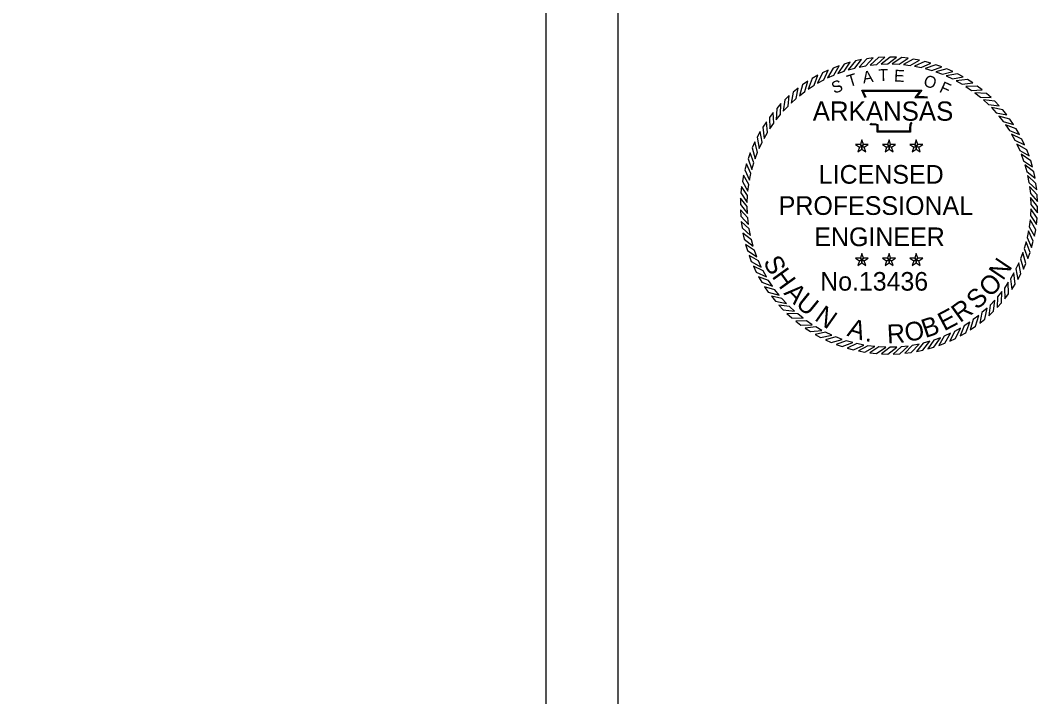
# Model space of a CAD drawing. Extents: x 759422 to 1402140, y 1662254 to 1956530.
# Drawn here: x 1401731.3 to 1402139.7, y 1955985.4 to 1956257.2 of the extents above; entities that cross this region are included whole.
import ezdxf

# ---------------------------------------------------------------- set-up
doc = ezdxf.new("R2010")
doc.units = 0
doc.layers.add('1', color=7, linetype='Continuous')
doc.layers.add('G-ANNO-SYMB', color=7, linetype='Continuous')

msp = doc.modelspace()

# ---------------------------------------------------------------- linework, layer by layer
at = {"layer": '1'}
msp.add_line((1401942.43, 1955459.2), (1401942.43, 1956501.52), dxfattribs=at)
msp.add_lwpolyline([(1401971.27, 1956530.36), (1400271.27, 1956530.36), (1400271.27, 1955430.36), (1401971.27, 1955430.36)], close=True, dxfattribs=at)
at = {"layer": 'G-ANNO-SYMB'}
for points in [[(1402073.67, 1956242.04), (1402071.13, 1956241.72), (1402068.01, 1956238.37), (1402070.73, 1956238.89)], [(1402078.34, 1956242.36), (1402075.78, 1956242.23), (1402072.41, 1956239.14), (1402075.17, 1956239.45)], [(1402083.03, 1956242.31), (1402080.46, 1956242.39), (1402076.86, 1956239.57), (1402079.63, 1956239.66)], [(1402087.69, 1956241.89), (1402085.14, 1956242.17), (1402081.33, 1956239.64), (1402084.1, 1956239.52)], [(1402060, 1956238.92), (1402057.6, 1956238), (1402055.35, 1956234.02), (1402057.88, 1956235.16)], [(1402064.47, 1956240.32), (1402062.01, 1956239.59), (1402059.45, 1956235.8), (1402062.06, 1956236.74)], [(1402069.04, 1956241.36), (1402066.53, 1956240.83), (1402063.68, 1956237.25), (1402066.35, 1956237.99)], [(1402092.31, 1956241.11), (1402089.79, 1956241.59), (1402085.79, 1956239.37), (1402088.54, 1956239.02)], [(1402096.86, 1956239.97), (1402094.38, 1956240.64), (1402090.22, 1956238.74), (1402092.93, 1956238.18)], [(1402101.3, 1956238.48), (1402098.88, 1956239.34), (1402094.58, 1956237.77), (1402097.24, 1956237)], [(1402105.6, 1956236.64), (1402103.26, 1956237.69), (1402098.86, 1956236.46), (1402101.45, 1956235.48)], [(1402051.46, 1956235.09), (1402049.23, 1956233.81), (1402047.63, 1956229.53), (1402049.95, 1956231.05)], [(1402055.65, 1956237.17), (1402053.33, 1956236.07), (1402051.4, 1956231.93), (1402053.83, 1956233.26)], [(1402109.75, 1956234.47), (1402107.5, 1956235.69), (1402103.01, 1956234.82), (1402105.52, 1956233.64)], [(1402043.62, 1956229.97), (1402041.62, 1956228.36), (1402040.71, 1956223.88), (1402042.76, 1956225.75)], [(1402047.44, 1956232.68), (1402045.32, 1956231.24), (1402044.06, 1956226.84), (1402046.25, 1956228.54)], [(1402113.72, 1956231.98), (1402111.57, 1956233.38), (1402107.03, 1956232.86), (1402109.44, 1956231.49)], [(1402117.48, 1956229.18), (1402115.45, 1956230.75), (1402110.88, 1956230.59), (1402113.17, 1956229.03)], [(1402040.02, 1956226.97), (1402038.16, 1956225.2), (1402037.6, 1956220.67), (1402039.5, 1956222.69)], [(1402121.01, 1956226.1), (1402119.11, 1956227.82), (1402114.54, 1956228.02), (1402116.7, 1956226.29)], [(1402036.68, 1956223.69), (1402034.95, 1956221.79), (1402034.75, 1956217.22), (1402036.49, 1956219.38)], [(1402124.29, 1956222.75), (1402122.53, 1956224.62), (1402117.99, 1956225.18), (1402120.01, 1956223.28)], [(1402127.29, 1956219.16), (1402125.68, 1956221.16), (1402121.2, 1956222.07), (1402123.07, 1956220.02)], [(1402033.6, 1956220.16), (1402032.03, 1956218.13), (1402032.19, 1956213.56), (1402033.75, 1956215.85)], [(1402130.01, 1956215.34), (1402128.56, 1956217.46), (1402124.16, 1956218.72), (1402125.86, 1956216.53)], [(1402030.8, 1956216.4), (1402029.4, 1956214.25), (1402029.92, 1956209.71), (1402031.29, 1956212.12)], [(1402132.41, 1956211.32), (1402131.13, 1956213.54), (1402126.85, 1956215.15), (1402128.37, 1956212.83)], [(1402028.31, 1956212.43), (1402027.08, 1956210.18), (1402027.95, 1956205.69), (1402029.13, 1956208.2)], [(1402069.14, 1956206.48), (1402069.75, 1956207.33), (1402069.14, 1956209.21), (1402068.53, 1956207.33)], [(1402080.05, 1956206.48), (1402080.66, 1956207.33), (1402080.05, 1956209.21), (1402079.44, 1956207.33)], [(1402090.96, 1956206.48), (1402091.57, 1956207.33), (1402090.96, 1956209.21), (1402090.35, 1956207.33)], [(1402134.49, 1956207.12), (1402133.39, 1956209.44), (1402129.25, 1956211.37), (1402130.59, 1956208.95)], [(1402026.14, 1956208.28), (1402025.09, 1956205.94), (1402026.31, 1956201.53), (1402027.29, 1956204.13)], [(1402069.14, 1956206.48), (1402068.53, 1956207.33), (1402066.55, 1956207.33), (1402068.15, 1956206.16)], [(1402069.14, 1956206.48), (1402068.15, 1956206.16), (1402067.54, 1956204.28), (1402069.14, 1956205.44)], [(1402069.14, 1956206.48), (1402070.13, 1956206.16), (1402071.73, 1956207.33), (1402069.75, 1956207.33)], [(1402069.14, 1956206.48), (1402069.14, 1956205.44), (1402070.74, 1956204.28), (1402070.13, 1956206.16)], [(1402080.05, 1956206.48), (1402079.44, 1956207.33), (1402077.46, 1956207.33), (1402079.06, 1956206.16)], [(1402080.05, 1956206.48), (1402079.06, 1956206.16), (1402078.45, 1956204.28), (1402080.05, 1956205.44)], [(1402080.05, 1956206.48), (1402081.04, 1956206.16), (1402082.64, 1956207.33), (1402080.66, 1956207.33)], [(1402080.05, 1956206.48), (1402080.05, 1956205.44), (1402081.65, 1956204.28), (1402081.04, 1956206.16)], [(1402090.96, 1956206.48), (1402090.35, 1956207.33), (1402088.36, 1956207.33), (1402089.97, 1956206.16)], [(1402090.96, 1956206.48), (1402089.97, 1956206.16), (1402089.36, 1956204.28), (1402090.96, 1956205.44)], [(1402090.96, 1956206.48), (1402091.95, 1956206.16), (1402093.55, 1956207.33), (1402091.57, 1956207.33)], [(1402090.96, 1956206.48), (1402090.96, 1956205.44), (1402092.56, 1956204.28), (1402091.95, 1956206.16)], [(1402136.24, 1956202.78), (1402135.32, 1956205.17), (1402131.35, 1956207.43), (1402132.49, 1956204.9)], [(1402024.3, 1956203.97), (1402023.44, 1956201.56), (1402025, 1956197.26), (1402025.78, 1956199.92)], [(1402137.64, 1956198.31), (1402136.92, 1956200.77), (1402133.12, 1956203.33), (1402134.06, 1956200.72)], [(1402022.81, 1956199.53), (1402022.14, 1956197.06), (1402024.03, 1956192.9), (1402024.59, 1956195.61)], [(1402138.68, 1956193.74), (1402138.16, 1956196.25), (1402134.58, 1956199.1), (1402135.31, 1956196.42)], [(1402021.66, 1956194.99), (1402021.19, 1956192.47), (1402023.41, 1956188.47), (1402023.75, 1956191.22)], [(1402139.37, 1956189.11), (1402139.04, 1956191.65), (1402135.69, 1956194.77), (1402136.21, 1956192.05)], [(1402020.88, 1956190.37), (1402020.61, 1956187.82), (1402023.13, 1956184.01), (1402023.26, 1956186.78)], [(1402139.68, 1956184.43), (1402139.56, 1956186.99), (1402136.47, 1956190.37), (1402136.77, 1956187.61)], [(1402020.46, 1956185.71), (1402020.39, 1956183.14), (1402023.21, 1956179.54), (1402023.12, 1956182.31)], [(1402139.63, 1956179.75), (1402139.71, 1956182.31), (1402136.89, 1956185.92), (1402136.98, 1956183.15)], [(1402020.41, 1956181.02), (1402020.54, 1956178.46), (1402023.63, 1956175.09), (1402023.33, 1956177.84)], [(1402139.22, 1956175.08), (1402139.49, 1956177.63), (1402136.97, 1956181.45), (1402136.84, 1956178.68)], [(1402020.73, 1956176.35), (1402021.06, 1956173.8), (1402024.41, 1956170.69), (1402023.89, 1956173.41)], [(1402138.43, 1956170.46), (1402138.91, 1956172.99), (1402136.69, 1956176.98), (1402136.34, 1956174.23)], [(1402137.29, 1956165.92), (1402137.96, 1956168.4), (1402136.07, 1956172.56), (1402135.5, 1956169.84)], [(1402021.42, 1956171.71), (1402021.94, 1956169.2), (1402025.52, 1956166.36), (1402024.79, 1956169.03)], [(1402135.8, 1956161.48), (1402136.66, 1956163.9), (1402135.1, 1956168.19), (1402134.32, 1956165.53)], [(1402022.46, 1956167.15), (1402023.18, 1956164.69), (1402026.97, 1956162.13), (1402026.03, 1956164.74)], [(1402023.86, 1956162.68), (1402024.77, 1956160.28), (1402028.75, 1956158.03), (1402027.61, 1956160.55)], [(1402069.14, 1956160.8), (1402068.53, 1956161.64), (1402066.55, 1956161.64), (1402068.15, 1956160.48)], [(1402069.14, 1956160.8), (1402068.15, 1956160.48), (1402067.54, 1956158.6), (1402069.14, 1956159.76)], [(1402069.14, 1956160.8), (1402069.75, 1956161.64), (1402069.14, 1956163.53), (1402068.53, 1956161.64)], [(1402069.14, 1956160.8), (1402070.13, 1956160.48), (1402071.73, 1956161.64), (1402069.75, 1956161.64)], [(1402069.14, 1956160.8), (1402069.14, 1956159.76), (1402070.74, 1956158.6), (1402070.13, 1956160.48)], [(1402080.05, 1956160.8), (1402079.44, 1956161.64), (1402077.46, 1956161.64), (1402079.06, 1956160.48)], [(1402080.05, 1956160.8), (1402079.06, 1956160.48), (1402078.45, 1956158.6), (1402080.05, 1956159.76)], [(1402080.05, 1956160.8), (1402080.66, 1956161.64), (1402080.05, 1956163.53), (1402079.44, 1956161.64)], [(1402080.05, 1956160.8), (1402081.04, 1956160.48), (1402082.64, 1956161.64), (1402080.66, 1956161.64)], [(1402080.05, 1956160.8), (1402080.05, 1956159.76), (1402081.65, 1956158.6), (1402081.04, 1956160.48)], [(1402090.96, 1956160.8), (1402090.35, 1956161.64), (1402088.36, 1956161.64), (1402089.97, 1956160.48)], [(1402090.96, 1956160.8), (1402089.97, 1956160.48), (1402089.36, 1956158.6), (1402090.96, 1956159.76)], [(1402090.96, 1956160.8), (1402091.57, 1956161.64), (1402090.96, 1956163.53), (1402090.35, 1956161.64)], [(1402090.96, 1956160.8), (1402091.95, 1956160.48), (1402093.55, 1956161.64), (1402091.57, 1956161.64)], [(1402090.96, 1956160.8), (1402090.96, 1956159.76), (1402092.56, 1956158.6), (1402091.95, 1956160.48)], [(1402133.96, 1956157.17), (1402135.01, 1956159.51), (1402133.79, 1956163.92), (1402132.81, 1956161.33)], [(1402025.61, 1956158.33), (1402026.71, 1956156.01), (1402030.85, 1956154.08), (1402029.51, 1956156.51)], [(1402131.79, 1956153.02), (1402133.02, 1956155.27), (1402132.14, 1956159.76), (1402130.96, 1956157.25)], [(1402027.69, 1956154.13), (1402028.97, 1956151.91), (1402033.25, 1956150.31), (1402031.73, 1956152.62)], [(1402126.5, 1956145.29), (1402128.07, 1956147.33), (1402127.91, 1956151.9), (1402126.35, 1956149.6)], [(1402129.3, 1956149.05), (1402130.7, 1956151.2), (1402130.18, 1956155.75), (1402128.81, 1956153.34)], [(1402030.09, 1956150.11), (1402031.54, 1956148), (1402035.94, 1956146.74), (1402034.24, 1956148.93)], [(1402123.42, 1956141.76), (1402125.14, 1956143.67), (1402125.34, 1956148.24), (1402123.61, 1956146.07)], [(1402032.81, 1956146.3), (1402034.42, 1956144.3), (1402038.9, 1956143.39), (1402037.03, 1956145.44)], [(1402120.08, 1956138.49), (1402121.94, 1956140.25), (1402122.5, 1956144.79), (1402120.6, 1956142.77)], [(1402035.81, 1956142.7), (1402037.57, 1956140.84), (1402042.11, 1956140.28), (1402040.09, 1956142.18)], [(1402116.48, 1956135.48), (1402118.48, 1956137.09), (1402119.39, 1956141.57), (1402117.34, 1956139.71)], [(1402039.09, 1956139.35), (1402040.99, 1956137.63), (1402045.56, 1956137.43), (1402043.39, 1956139.17)], [(1402042.62, 1956136.27), (1402044.65, 1956134.71), (1402049.22, 1956134.87), (1402046.92, 1956136.42)], [(1402108.64, 1956130.37), (1402110.87, 1956131.64), (1402112.47, 1956135.93), (1402110.15, 1956134.4)], [(1402112.66, 1956132.77), (1402114.78, 1956134.22), (1402116.04, 1956138.61), (1402113.85, 1956136.92)], [(1402046.38, 1956133.48), (1402048.52, 1956132.08), (1402053.07, 1956132.59), (1402050.66, 1956133.97)], [(1402050.34, 1956130.99), (1402052.6, 1956129.76), (1402057.08, 1956130.63), (1402054.58, 1956131.81)], [(1402100.1, 1956126.54), (1402102.5, 1956127.45), (1402104.75, 1956131.43), (1402102.22, 1956130.29)], [(1402104.45, 1956128.28), (1402106.76, 1956129.38), (1402108.7, 1956133.53), (1402106.27, 1956132.19)], [(1402054.49, 1956128.82), (1402056.84, 1956127.77), (1402061.24, 1956128.99), (1402058.65, 1956129.97)], [(1402058.8, 1956126.98), (1402061.22, 1956126.12), (1402065.52, 1956127.68), (1402062.85, 1956128.45)], [(1402091.06, 1956124.09), (1402093.57, 1956124.62), (1402096.42, 1956128.2), (1402093.75, 1956127.47)], [(1402095.63, 1956125.14), (1402098.09, 1956125.86), (1402100.65, 1956129.65), (1402098.04, 1956128.71)], [(1402063.24, 1956125.48), (1402065.72, 1956124.81), (1402069.88, 1956126.71), (1402067.17, 1956127.27)], [(1402067.79, 1956124.34), (1402070.31, 1956123.87), (1402074.31, 1956126.09), (1402071.56, 1956126.43)], [(1402072.4, 1956123.56), (1402074.96, 1956123.29), (1402078.77, 1956125.81), (1402076, 1956125.94)], [(1402077.07, 1956123.14), (1402079.63, 1956123.07), (1402083.24, 1956125.88), (1402080.47, 1956125.8)], [(1402081.75, 1956123.09), (1402084.32, 1956123.22), (1402087.69, 1956126.31), (1402084.93, 1956126)], [(1402086.43, 1956123.41), (1402088.97, 1956123.74), (1402092.09, 1956127.08), (1402089.37, 1956126.56)]]:
    msp.add_lwpolyline(points, close=True, dxfattribs=at)
for points in [[(1402070.49, 1956226.03), (1402069.1, 1956229.04), (1402093.16, 1956229.05), (1402091.15, 1956226.53), (1402092.79, 1956226.55), (1402094.15, 1956226.57), (1402095.52, 1956226.42)], [(1402070.84, 1956226.19), (1402069.7, 1956228.66), (1402092.37, 1956228.67), (1402090.36, 1956226.14), (1402092.79, 1956226.17), (1402094.14, 1956226.18), (1402095.48, 1956226.04)], [(1402089.37, 1956215.94), (1402088.96, 1956215.61), (1402088.83, 1956215.11), (1402088.69, 1956213.86), (1402088.69, 1956212.2), (1402075.26, 1956212.2), (1402075.26, 1956214.44), (1402075.26, 1956214.94), (1402074.71, 1956215.11), (1402072.8, 1956215.11), (1402072.46, 1956215.63)], [(1402089.13, 1956216.24), (1402088.63, 1956215.83), (1402088.45, 1956215.18), (1402088.31, 1956213.88), (1402088.31, 1956212.58), (1402075.64, 1956212.58), (1402075.64, 1956214.44), (1402075.64, 1956215.23), (1402074.77, 1956215.49), (1402073.01, 1956215.49), (1402072.78, 1956215.84)]]:
    msp.add_lwpolyline(points, dxfattribs=at)

# ---------------------------------------------------------------- texts
for s, height, rotation, p in [('T', 4.75, 1.4789, (1402075.89, 1956232.76)), ('T', 4.75, 16.9015, (1402063.99, 1956230.32)), ('A', 4.75, 8.6788, (1402069.76, 1956231.82)), ('E', 4.75, 356.672, (1402081.96, 1956232.62)), ('O', 4.75, 341.2218, (1402093.49, 1956230.99)), ('S', 4.75, 19.7726, (1402057.96, 1956227.61)), ('F', 4.75, 335.3628, (1402099.89, 1956228.49)), ('ARKANSAS', 7.747, 360, (1402049.43, 1956216.81)), ('LICENSED', 7.5, 360, (1402051.84, 1956191.52)), ('PROFESSIONAL', 7.5, 360, (1402035.76, 1956178.98)), ('ENGINEER', 7.5, 360, (1402050.05, 1956166.43)), ('S', 7.5, 298.1636, (1402029.37, 1956160.13)), ('N', 7.5, 56.1007, (1402125.79, 1956152.29)), ('H', 7.5, 305.619, (1402032.79, 1956154.25)), ('No.13436', 7.47, 360, (1402052.42, 1956148.56)), ('O', 7.5, 44.7757, (1402120.58, 1956145.54)), ('A', 7.5, 313.4472, (1402037.55, 1956147.41)), ('U', 7.5, 320.9026, (1402042.23, 1956142.52)), ('S', 7.5, 43.4878, (1402115.43, 1956140.57)), ('R', 7.5, 35.6597, (1402108.53, 1956135.47)), ('N', 7.5, 324.9326, (1402049.78, 1956136.93)), ('E', 7.5, 27.8315, (1402102.19, 1956132.15)), ('A', 7.5, 343.0991, (1402062.86, 1956130.5)), ('O', 7.5, 11.4296, (1402087.1, 1956127.85)), ('B', 7.5, 18.885, (1402094.62, 1956129.44)), ('R', 7.5, 3.2287, (1402079.43, 1956127.36)), ('.', 7.5, 351.3, (1402070.23, 1956128.31))]:
    msp.add_text(s, height=height, rotation=rotation, dxfattribs=at).set_placement(p)

doc.saveas('drawing.dxf')
